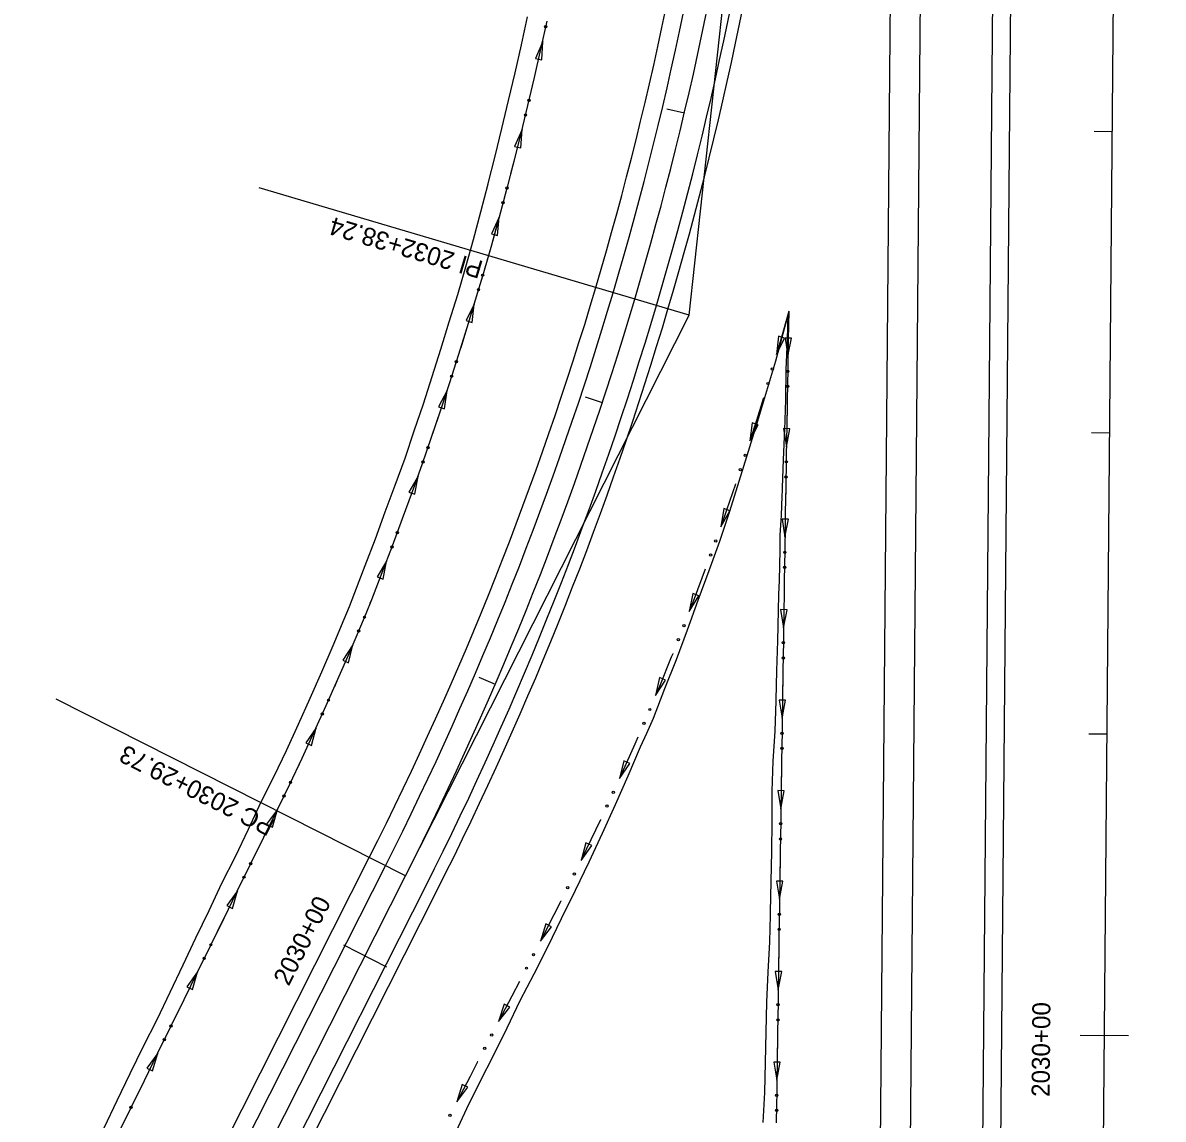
# Model space of a CAD drawing. Extents: x 1611108 to 1749517, y 619561 to 797725.
# Drawn here: x 1713228.5 to 1713607, y 759994 to 760357.9 of the extents above; entities that cross this region are included whole.
import ezdxf

# ---------------------------------------------------------------- set-up
doc = ezdxf.new("R2010")
doc.units = 0
for name, color, linetype in [('R_Ditch', 7, 'Continuous'), ('R_Horz Alg', 7, 'Continuous'), ('R_Horz Alg Annot', 7, 'Continuous'), ('R_Horz Alg Stationing', 7, 'Continuous'), ('R_Proposed Const Limits', 7, 'Continuous'), ('R_Proposed Road', 7, 'Continuous'), ('R_Proposed_SHLDR', 7, 'Continuous'), ('S_EDGE_PAVEMENT', 7, 'Continuous')]:
    doc.layers.add(name, color=color, linetype=linetype)

msp = doc.modelspace()

# ---------------------------------------------------------------- linework, layer by layer
at = {"layer": 'R_Ditch'}
for p, q in [((1713401.05, 760351.66), (1713398.69, 760346.04)), ((1713400.76, 760345.57), (1713401.05, 760351.66)), ((1713398.69, 760346.04), (1713400.76, 760345.57)), ((1713394.21, 760322.41), (1713391.71, 760316.85)), ((1713393.77, 760316.34), (1713394.21, 760322.41)), ((1713391.71, 760316.85), (1713393.77, 760316.34)), ((1713386.64, 760293.34), (1713384.02, 760287.85)), ((1713386.05, 760287.28), (1713386.64, 760293.34)), ((1713384.02, 760287.85), (1713386.05, 760287.28)), ((1713378.35, 760264.47), (1713375.6, 760259.04)), ((1713377.63, 760258.42), (1713378.35, 760264.47)), ((1713375.6, 760259.04), (1713377.63, 760258.42)), ((1713479.32, 760253.81), (1713478.66, 760247.75)), ((1713478.66, 760247.75), (1713481.35, 760253.22)), ((1713481.35, 760253.22), (1713479.32, 760253.81)), ((1713483.63, 760253.17), (1713481.51, 760253.21)), ((1713481.51, 760253.21), (1713482.47, 760247.19)), ((1713482.47, 760247.19), (1713483.63, 760253.17)), ((1713369.36, 760235.81), (1713366.48, 760230.45)), ((1713368.49, 760229.78), (1713369.36, 760235.81)), ((1713366.48, 760230.45), (1713368.49, 760229.78)), ((1713470.62, 760225.09), (1713469.78, 760219.06)), ((1713469.78, 760219.06), (1713472.63, 760224.44)), ((1713472.63, 760224.44), (1713470.62, 760225.09)), ((1713483.12, 760223.14), (1713481.01, 760223.17)), ((1713481.01, 760223.17), (1713481.96, 760217.16)), ((1713481.96, 760217.16), (1713483.12, 760223.14)), ((1713359.66, 760207.39), (1713356.65, 760202.09)), ((1713358.64, 760201.38), (1713359.66, 760207.39)), ((1713356.65, 760202.09), (1713358.64, 760201.38)), ((1713461.13, 760196.62), (1713460.13, 760190.61)), ((1713463.13, 760195.92), (1713461.13, 760196.62)), ((1713460.13, 760190.61), (1713463.13, 760195.92)), ((1713482.63, 760193.11), (1713480.52, 760193.14)), ((1713480.52, 760193.14), (1713481.48, 760187.12)), ((1713481.48, 760187.12), (1713482.63, 760193.11)), ((1713349.25, 760179.21), (1713346.12, 760173.98)), ((1713348.1, 760173.23), (1713349.25, 760179.21)), ((1713346.12, 760173.98), (1713348.1, 760173.23)), ((1713450.88, 760168.42), (1713449.7, 760162.44)), ((1713449.7, 760162.44), (1713452.85, 760167.66)), ((1713452.85, 760167.66), (1713450.88, 760168.42)), ((1713482.16, 760163.07), (1713480.04, 760163.1)), ((1713480.04, 760163.1), (1713481.01, 760157.09)), ((1713481.01, 760157.09), (1713482.16, 760163.07)), ((1713338.03, 760151.35), (1713334.66, 760146.27)), ((1713336.6, 760145.42), (1713338.03, 760151.35)), ((1713334.66, 760146.27), (1713336.6, 760145.42)), ((1713439.85, 760140.51), (1713438.51, 760134.57)), ((1713438.51, 760134.57), (1713441.81, 760139.69)), ((1713441.81, 760139.69), (1713439.85, 760140.51)), ((1713481.7, 760133.04), (1713479.59, 760133.07)), ((1713479.59, 760133.07), (1713480.56, 760127.05)), ((1713480.56, 760127.05), (1713481.7, 760133.04)), ((1713325.85, 760123.89), (1713322.37, 760118.89)), ((1713324.29, 760118), (1713325.85, 760123.89)), ((1713322.37, 760118.89), (1713324.29, 760118)), ((1713428.01, 760112.93), (1713426.54, 760107.02)), ((1713429.95, 760112.07), (1713428.01, 760112.93)), ((1713426.54, 760107.02), (1713429.95, 760112.07)), ((1713481.26, 760103), (1713479.14, 760103.03)), ((1713479.14, 760103.03), (1713480.11, 760097.02)), ((1713480.11, 760097.02), (1713481.26, 760103)), ((1713312.99, 760096.75), (1713309.4, 760091.83)), ((1713311.3, 760090.89), (1713312.99, 760096.75)), ((1713309.4, 760091.83), (1713311.3, 760090.89)), ((1713415.41, 760085.7), (1713413.77, 760079.83)), ((1713413.77, 760079.83), (1713417.32, 760084.79)), ((1713417.32, 760084.79), (1713415.41, 760085.7)), ((1713480.82, 760072.97), (1713478.7, 760073)), ((1713478.7, 760073), (1713479.67, 760066.98)), ((1713479.67, 760066.98), (1713480.82, 760072.97)), ((1713299.75, 760069.78), (1713296.15, 760064.87)), ((1713298.05, 760063.93), (1713299.75, 760069.78)), ((1713296.15, 760064.87), (1713298.05, 760063.93)), ((1713402.07, 760058.82), (1713400.27, 760053)), ((1713400.27, 760053), (1713403.95, 760057.85)), ((1713403.95, 760057.85), (1713402.07, 760058.82)), ((1713286.51, 760042.82), (1713282.91, 760037.9)), ((1713284.81, 760036.97), (1713286.51, 760042.82)), ((1713480.38, 760042.93), (1713478.26, 760042.96)), ((1713478.26, 760042.96), (1713479.23, 760036.95)), ((1713479.23, 760036.95), (1713480.38, 760042.93)), ((1713282.91, 760037.9), (1713284.81, 760036.97)), ((1713388.24, 760032.16), (1713386.4, 760026.35)), ((1713386.4, 760026.35), (1713390.11, 760031.19)), ((1713390.11, 760031.19), (1713388.24, 760032.16)), ((1713273.26, 760015.86), (1713269.67, 760010.94)), ((1713271.57, 760010.01), (1713273.26, 760015.86)), ((1713269.67, 760010.94), (1713271.57, 760010.01)), ((1713479.93, 760012.9), (1713477.82, 760012.93)), ((1713477.82, 760012.93), (1713478.79, 760006.92)), ((1713478.79, 760006.92), (1713479.93, 760012.9)), ((1713374.37, 760005.52), (1713372.54, 759999.71)), ((1713372.54, 759999.71), (1713376.24, 760004.54)), ((1713376.24, 760004.54), (1713374.37, 760005.52))]:
    msp.add_line(p, q, dxfattribs=at)
for points in [[(1713260, 759988.86), (1713264.41, 759997.83), (1713268.82, 760006.81), (1713273.23, 760015.79), (1713277.64, 760024.76), (1713282.04, 760033.74), (1713286.45, 760042.72), (1713290.86, 760051.69), (1713295.27, 760060.67), (1713299.68, 760069.65), (1713304.09, 760078.62), (1713308.5, 760087.6), (1713312.9, 760096.56), (1713317.08, 760105.19), (1713321.19, 760113.84), (1713325.22, 760122.53), (1713329.19, 760131.25), (1713333.09, 760140), (1713336.91, 760148.78), (1713340.67, 760157.59), (1713342.42, 760161.77), (1713344.29, 760166.45), (1713347.79, 760175.37), (1713351.21, 760184.31), (1713354.56, 760193.28), (1713357.84, 760202.27), (1713361.04, 760211.29), (1713364.18, 760220.32), (1713367.24, 760229.39), (1713370.23, 760238.47), (1713373.15, 760247.58), (1713376, 760256.71), (1713378.77, 760265.86), (1713381.48, 760275.02), (1713384.11, 760284.21), (1713386.66, 760293.42), (1713389.15, 760302.65), (1713389.2, 760302.85), (1713391.56, 760311.9), (1713393.89, 760321.17), (1713396.16, 760330.45), (1713398.35, 760339.75), (1713400.46, 760349.06), (1713402.51, 760358.4)], [(1713397.71, 760337.04), (1713398.35, 760339.75), (1713400.46, 760349.06), (1713401.03, 760351.66)], [(1713397.7, 760337), (1713397.71, 760337.04)], [(1713390.51, 760307.88), (1713391.56, 760311.9), (1713393.89, 760321.17), (1713394.2, 760322.41)], [(1713390.5, 760307.84), (1713390.51, 760307.88)], [(1713382.59, 760278.9), (1713384.11, 760284.21), (1713386.64, 760293.34)], [(1713382.58, 760278.87), (1713382.59, 760278.9)], [(1713373.95, 760250.13), (1713376, 760256.71), (1713378.35, 760264.47)], [(1713482.72, 760262.19), (1713481.01, 760255.84), (1713478.66, 760247.75)], [(1713482.72, 760262.19), (1713482.56, 760252.75), (1713482.47, 760247.19)], [(1713373.94, 760250.1), (1713373.95, 760250.13)], [(1713364.61, 760221.59), (1713367.24, 760229.39), (1713369.36, 760235.81)], [(1713474.31, 760233.35), (1713471.97, 760225.85), (1713469.78, 760219.06)], [(1713474.32, 760233.39), (1713474.31, 760233.35)], [(1713482.21, 760232.16), (1713482.06, 760222.8), (1713482.06, 760222.76), (1713482.05, 760222.37), (1713482.03, 760221.08), (1713482.02, 760220.47), (1713481.96, 760217.16)], [(1713482.21, 760232.19), (1713482.21, 760232.16)], [(1713364.59, 760221.55), (1713364.61, 760221.59)], [(1713354.56, 760193.28), (1713357.84, 760202.27), (1713359.66, 760207.39)], [(1713465.05, 760204.78), (1713462.08, 760196.14), (1713460.13, 760190.61)], [(1713465.06, 760204.82), (1713465.05, 760204.78)], [(1713481.72, 760202.12), (1713481.7, 760200.69), (1713481.59, 760194.32), (1713481.57, 760192.76), (1713481.49, 760187.77), (1713481.48, 760187.12)], [(1713481.72, 760202.16), (1713481.72, 760202.12)], [(1713354.54, 760193.24), (1713354.56, 760193.28), (1713354.56, 760193.28)], [(1713343.81, 760165.23), (1713344.29, 760166.45), (1713347.79, 760175.37), (1713349.25, 760179.21)], [(1713455.01, 760176.47), (1713451.35, 760166.71), (1713449.7, 760162.44)], [(1713455.03, 760176.51), (1713455.02, 760176.49), (1713455.01, 760176.47)], [(1713481.24, 760172.09), (1713481.18, 760168.09), (1713481.1, 760162.76), (1713481.01, 760157.09)], [(1713481.24, 760172.12), (1713481.24, 760172.09)], [(1713343.79, 760165.2), (1713343.81, 760165.23)], [(1713332.02, 760137.61), (1713333.09, 760140), (1713336.91, 760148.78), (1713338.01, 760151.36)], [(1713444.2, 760148.45), (1713443.73, 760147.27), (1713439.78, 760137.6), (1713438.51, 760134.57)], [(1713444.21, 760148.48), (1713444.2, 760148.45)], [(1713480.78, 760142.05), (1713480.65, 760133.12), (1713480.64, 760132.77), (1713480.56, 760127.05)], [(1713480.78, 760142.09), (1713480.78, 760142.05)], [(1713332, 760137.57), (1713332.02, 760137.61)], [(1713319.51, 760110.3), (1713321.19, 760113.84), (1713325.22, 760122.53), (1713325.84, 760123.89)], [(1713432.62, 760120.73), (1713431.6, 760118.39), (1713427.36, 760108.85), (1713426.52, 760107.03)], [(1713432.64, 760120.77), (1713432.62, 760120.73)], [(1713319.49, 760110.26), (1713319.51, 760110.3)], [(1713480.34, 760112.02), (1713480.2, 760102.77), (1713480.11, 760097.02)], [(1713480.34, 760112.06), (1713480.34, 760112.02)], [(1713306.38, 760083.28), (1713308.5, 760087.6), (1713312.9, 760096.56), (1713312.99, 760096.75)], [(1713420.22, 760093.37), (1713418.6, 760089.9), (1713414.08, 760080.49), (1713413.76, 760079.84)], [(1713420.24, 760093.41), (1713420.22, 760093.37)], [(1713306.36, 760083.25), (1713306.38, 760083.28)], [(1713479.89, 760081.98), (1713479.76, 760072.77), (1713479.67, 760066.98)], [(1713479.89, 760082.02), (1713479.89, 760081.98)], [(1713293.14, 760056.32), (1713295.27, 760060.67), (1713299.68, 760069.65), (1713299.75, 760069.78)], [(1713407.09, 760066.36), (1713404.79, 760061.8), (1713400.27, 760053)], [(1713407.1, 760066.4), (1713407.09, 760066.36)], [(1713293.12, 760056.29), (1713293.14, 760056.32)], [(1713479.45, 760051.95), (1713479.32, 760042.77), (1713479.23, 760036.95)], [(1713479.45, 760051.99), (1713479.45, 760051.95)], [(1713279.89, 760029.36), (1713282.04, 760033.74), (1713286.45, 760042.72), (1713286.51, 760042.82)], [(1713393.33, 760039.66), (1713390.78, 760034.77), (1713386.4, 760026.35)], [(1713393.35, 760039.69), (1713393.33, 760039.66)], [(1713279.88, 760029.33), (1713279.89, 760029.36)], [(1713479.01, 760021.91), (1713478.87, 760012.78), (1713478.79, 760006.92)], [(1713479.01, 760021.95), (1713479.01, 760021.91)], [(1713266.65, 760002.4), (1713268.82, 760006.81), (1713273.23, 760015.79), (1713273.26, 760015.86)], [(1713379.46, 760013.01), (1713376.93, 760008.15), (1713372.54, 759999.71)], [(1713379.48, 760013.05), (1713379.46, 760013.01)], [(1713266.63, 760002.36), (1713266.65, 760002.4)]]:
    msp.add_lwpolyline(points, dxfattribs=at)
for centre in [(1713402.07, 760356.56), (1713396.52, 760332.16), (1713395.35, 760327.29), (1713389.21, 760303.03), (1713387.91, 760298.19), (1713381.16, 760274.09), (1713379.75, 760269.28), (1713372.4, 760245.36), (1713477.27, 760242.94), (1713482.42, 760242.19), (1713370.87, 760240.58), (1713475.82, 760238.15), (1713482.33, 760237.18), (1713362.94, 760216.85), (1713361.29, 760212.12), (1713468.27, 760214.28), (1713481.92, 760212.15), (1713466.68, 760209.53), (1713481.84, 760207.14), (1713352.77, 760188.59), (1713458.49, 760185.88), (1713351.01, 760183.9), (1713456.77, 760181.18), (1713481.44, 760182.12), (1713481.36, 760177.11), (1713341.89, 760160.59), (1713447.93, 760157.76), (1713339.94, 760155.98), (1713446.09, 760153.1), (1713480.97, 760152.08), (1713480.89, 760147.07), (1713329.94, 760133.03), (1713327.88, 760128.47), (1713436.61, 760129.94), (1713434.65, 760125.33), (1713480.52, 760122.05), (1713480.45, 760117.04), (1713317.32, 760105.78), (1713315.14, 760101.27), (1713424.48, 760102.46), (1713422.38, 760097.91), (1713480.08, 760092.01), (1713480, 760087), (1713304.13, 760078.79), (1713411.59, 760075.33), (1713301.92, 760074.29), (1713409.38, 760070.83), (1713479.63, 760061.98), (1713479.56, 760056.97), (1713290.89, 760051.83), (1713397.99, 760048.54), (1713288.68, 760047.33), (1713395.68, 760044.1), (1713479.19, 760031.94), (1713479.12, 760026.93), (1713277.65, 760024.87), (1713384.12, 760021.9), (1713275.44, 760020.37), (1713381.81, 760017.45), (1713478.75, 760001.91), (1713264.4, 759997.91), (1713370.26, 759995.25), (1713478.68, 759996.9)]:
    msp.add_circle(centre, 0.375, dxfattribs=at)
at = {"layer": 'R_Horz Alg'}
for p, q in [((1713561.33, 757021.94), (1713607.03, 762259.43)), ((1713240.51, 759847.35), (1713355.53, 760074.71))]:
    msp.add_line(p, q, dxfattribs=at)
msp.add_arc((1712333, 760591.97), 1145.92, 333.16667, 353.79167, dxfattribs=at)
at = {"layer": 'R_Horz Alg Annot'}
for points in [[(1713355.53, 760074.71), (1713449.65, 760260.77), (1713472.2, 760468.05)], [(1713449.65, 760260.77), (1713306.98, 760303.08)], [(1713355.53, 760074.71), (1713239.53, 760133.39)]]:
    msp.add_lwpolyline(points, dxfattribs=at)
at = {"layer": 'R_Horz Alg Stationing'}
for points in [[(1713442.25, 760329.35), (1713448.09, 760327.97)], [(1713584.12, 760321.87), (1713590.12, 760321.82)], [(1713415.14, 760233.68), (1713420.84, 760231.79)], [(1713583.25, 760221.87), (1713589.25, 760221.82)], [(1713379.8, 760140.72), (1713385.31, 760138.35)], [(1713582.38, 760121.88), (1713588.38, 760121.83)], [(1713334.97, 760051.79), (1713349.25, 760044.57)], [(1713579.5, 760021.9), (1713595.5, 760021.76)]]:
    msp.add_lwpolyline(points, dxfattribs=at)
at = {"layer": 'R_Proposed Const Limits'}
for points in [[(1713255.48, 759991.15), (1713259.75, 760000.19), (1713264.13, 760009.18), (1713268.49, 760018.18), (1713273.09, 760027.07), (1713277.41, 760036.09), (1713281.65, 760045.15), (1713285.9, 760054.21), (1713290.29, 760063.19), (1713294.53, 760072.25), (1713299.08, 760081.16), (1713303.42, 760090.17), (1713307.55, 760099.27), (1713311.89, 760107.76), (1713315.97, 760116.37), (1713319.95, 760125.03), (1713323.85, 760133.72), (1713327.69, 760142.44), (1713331.46, 760151.19), (1713335.16, 760159.97), (1713336.88, 760164.13), (1713338.72, 760168.8), (1713342.15, 760177.68), (1713345.55, 760186.58), (1713348.78, 760195.53), (1713352.13, 760204.44), (1713355.35, 760213.39), (1713358.43, 760222.4), (1713361.43, 760231.42), (1713364.36, 760240.47), (1713367.19, 760249.55), (1713369.97, 760258.64), (1713372.86, 760267.7), (1713375.56, 760276.81), (1713378.08, 760285.98), (1713380.55, 760295.16), (1713382.9, 760304.36), (1713382.95, 760304.57), (1713385.25, 760313.57), (1713387.52, 760322.79), (1713389.75, 760332.02), (1713391.91, 760341.27), (1713393.99, 760350.54), (1713395.99, 760359.82)], [(1713371.64, 759988.42), (1713375.86, 759997.49), (1713380.24, 760006.48), (1713384.83, 760015.36), (1713389.26, 760024.33), (1713393.62, 760033.33), (1713398.18, 760042.23), (1713402.74, 760051.14), (1713407.29, 760060.56), (1713411.95, 760069.93), (1713416.45, 760079.37), (1713420.85, 760088.86), (1713425.19, 760098.38), (1713429.4, 760107.95), (1713433.55, 760117.55), (1713435.6, 760122.06), (1713437.81, 760127.1), (1713441.6, 760136.86), (1713445.49, 760146.56), (1713449.12, 760156.37), (1713452.7, 760166.2), (1713456.28, 760176.02), (1713459.87, 760185.83), (1713463.2, 760195.74), (1713466.3, 760205.73), (1713469.4, 760215.71), (1713472.42, 760225.71), (1713475.44, 760235.71), (1713478.48, 760245.7), (1713482.55, 760260.97)], [(1713474.27, 759992.82), (1713474.83, 760002.81), (1713475.02, 760012.81), (1713475.19, 760022.81), (1713475.5, 760032.81), (1713475.93, 760042.8), (1713476.42, 760052.8), (1713476.65, 760061.69), (1713476.68, 760062.8), (1713476.94, 760072.8), (1713477.17, 760082.79), (1713477.18, 760092.8), (1713477.25, 760102.79), (1713477.57, 760112.79), (1713478.23, 760122.79), (1713478.51, 760132.79), (1713478.52, 760133.14), (1713478.79, 760142.78), (1713479.06, 760152.78), (1713479.34, 760162.78), (1713479.49, 760168.11), (1713479.62, 760172.78), (1713479.9, 760182.77), (1713479.91, 760185.83), (1713479.92, 760187.78), (1713480.22, 760192.77), (1713480.31, 760194.33), (1713480.56, 760200.7), (1713480.64, 760202.77), (1713480.67, 760203.67), (1713481.03, 760212.77), (1713481.33, 760220.47), (1713481.35, 760221.09), (1713481.4, 760222.38), (1713481.42, 760222.76), (1713481.42, 760222.8), (1713481.76, 760232.76), (1713481.89, 760242.76), (1713482.31, 760252.76), (1713482.55, 760260.97)]]:
    msp.add_lwpolyline(points, dxfattribs=at)
at = {"layer": 'R_Proposed Road'}
for p, q in [((1713541.83, 759372.2), (1713567.03, 762259.78)), ((1713547.83, 759372.15), (1713573.03, 762259.72)), ((1713507.84, 759372.5), (1713517.89, 760524.26)), ((1713517.83, 759372.41), (1713527.89, 760524.17)), ((1713233.82, 759850.73), (1713348.83, 760078.1)), ((1713247.2, 759843.96), (1713362.22, 760071.33))]:
    msp.add_line(p, q, dxfattribs=at)
for radius in [1138.42, 1153.42]:
    msp.add_arc((1712333, 760591.97), radius, 333.16667, 353.79167, dxfattribs=at)
at = {"layer": 'R_Proposed_SHLDR'}
for p, q in [((1713228.47, 759853.44), (1713343.48, 760080.81)), ((1713250.77, 759842.16), (1713365.79, 760069.52))]:
    msp.add_line(p, q, dxfattribs=at)
for radius in [1132.42, 1157.42]:
    msp.add_arc((1712333, 760591.97), radius, 333.16667, 353.79167, dxfattribs=at)
at = {"layer": 'S_EDGE_PAVEMENT'}
msp.add_lwpolyline([(1713482.72, 760262.19), (1713482.56, 760252.75), (1713482.39, 760242.76), (1713482.22, 760232.76), (1713482.06, 760222.8), (1713482.06, 760222.76), (1713482.05, 760222.37), (1713482.03, 760221.08), (1713482.02, 760220.47), (1713481.89, 760212.76), (1713481.74, 760203.66), (1713481.73, 760202.76), (1713481.7, 760200.69), (1713481.59, 760194.32), (1713481.57, 760192.76), (1713481.49, 760187.77), (1713481.46, 760185.82), (1713481.41, 760182.76), (1713481.25, 760172.76), (1713481.18, 760168.09), (1713481.1, 760162.76), (1713480.94, 760152.76), (1713480.79, 760142.77), (1713480.65, 760133.12), (1713480.64, 760132.77), (1713480.49, 760122.77), (1713480.35, 760112.77), (1713480.2, 760102.77), (1713480.05, 760092.77), (1713479.91, 760082.77), (1713479.76, 760072.77), (1713479.61, 760062.77), (1713479.59, 760061.67), (1713479.46, 760052.77), (1713479.32, 760042.77), (1713479.17, 760032.78), (1713479.02, 760022.78), (1713478.87, 760012.78), (1713478.73, 760002.78), (1713478.67, 759998.59), (1713478.58, 759992.78)], dxfattribs=at)

# ---------------------------------------------------------------- texts
at = {"layer": 'R_Horz Alg Annot'}
for s, rotation, p in [('PI 2032+38.24', 163.4792, (1713381.65, 760278.61)), ('PC 2030+29.73', 153.1667, (1713312.57, 760093.08))]:
    msp.add_text(s, height=6, rotation=rotation, dxfattribs=at).set_placement(p)
at = {"layer": 'R_Horz Alg Stationing'}
for rotation, p in [(63.1667, (1713316.73, 760037.89)), (89.5, (1713569.33, 760001.34))]:
    msp.add_text('2030+00', height=6, rotation=rotation, dxfattribs=at).set_placement(p)

doc.saveas('drawing.dxf')
